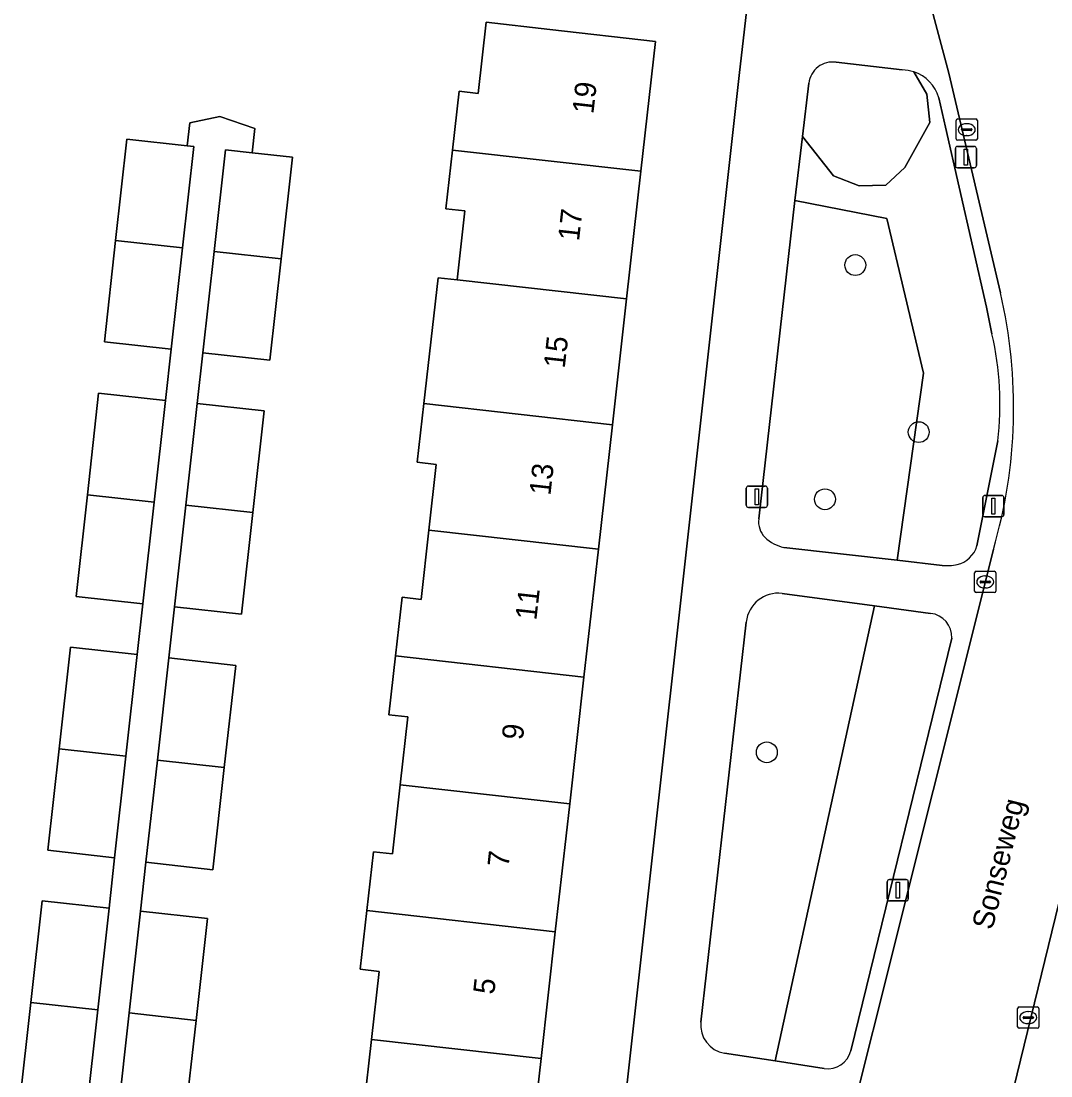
# Model space of a CAD drawing. Extents: x 162026 to 163502, y 387295 to 388169.
# Drawn here: x 162444.62 to 162492.97, y 387651.13 to 387700.63 of the extents above; entities that cross this region are included whole.
import ezdxf

# ---------------------------------------------------------------- set-up
doc = ezdxf.new("R2010")
doc.units = 0
for name, color, linetype in [('IMGEO_Boom', 7, 'Continuous'), ('IMGEO_Erf', 7, 'Continuous'), ('IMGEO_Groenvoorziening', 7, 'Continuous'), ('IMGEO_Kolk', 7, 'Continuous'), ('IMGEO_Lichtmast', 7, 'Continuous'), ('IMGEO_Openbare_ruimte_label', 7, 'Continuous'), ('IMGEO_Pand', 7, 'Continuous'), ('IMGEO_Pand_nummerreeks', 7, 'Continuous'), ('IMGEO_Rijbaan_lokaal_open', 7, 'Continuous'), ('IMGEO_Voetpad_open', 7, 'Continuous')]:
    doc.layers.add(name, color=color, linetype=linetype)

msp = doc.modelspace()

# ---------------------------------------------------------------- linework, layer by layer
at = {"layer": 'IMGEO_Boom'}
for centre in [(162483.784, 387689.183), (162486.762, 387681.344), (162482.36, 387678.19), (162479.63, 387666.315)]:
    msp.add_circle(centre, 0.489, dxfattribs=at)
at = {"layer": 'IMGEO_Erf'}
for points in [[(162471.82, 387639.553), (162478.34, 387698.075), (162483.821, 387745.82)], [(162460.711, 387649.647), (162461.071, 387652.841), (162461.43, 387656.029), (162460.536, 387656.13), (162460.847, 387658.889), (162461.158, 387661.648), (162462.052, 387661.547), (162462.417, 387664.785), (162462.776, 387667.976), (162461.882, 387668.077), (162462.193, 387670.836), (162462.504, 387673.595), (162463.398, 387673.494), (162463.764, 387676.741), (162464.112, 387679.827), (162463.218, 387679.928), (162463.529, 387682.687), (162464.194, 387688.589), (162465.088, 387688.488), (162465.452, 387691.722), (162464.558, 387691.823), (162464.869, 387694.582), (162465.18, 387697.341), (162466.074, 387697.24), (162466.45, 387700.58), (162469.441, 387700.243), (162474.409, 387699.683), (162473.722, 387693.585), (162473.047, 387687.592), (162472.382, 387681.69), (162471.723, 387675.844), (162471.046, 387669.839), (162470.376, 387663.889), (162469.7, 387657.892), (162469.03, 387651.945), (162468.359, 387645.992)], [(162444.545, 387649.799), (162445.077, 387654.579), (162445.608, 387659.349), (162448.749, 387659), (162449.012, 387661.368), (162445.872, 387661.718), (162446.401, 387666.478), (162446.932, 387671.249), (162450.073, 387670.899), (162450.338, 387673.285), (162447.198, 387673.634), (162447.729, 387678.404), (162448.259, 387683.175), (162451.4, 387682.825), (162451.668, 387685.229), (162448.527, 387685.579), (162449.057, 387690.338), (162449.586, 387695.099), (162452.42, 387694.784), (162452.54, 387695.863), (162453.951, 387696.158), (162455.587, 387695.598), (162455.462, 387694.457), (162457.357, 387694.245), (162456.824, 387689.475), (162456.293, 387684.719), (162453.153, 387685.07), (162452.886, 387682.687), (162456.027, 387682.336), (162455.494, 387677.566), (162454.961, 387672.794), (162451.821, 387673.144), (162451.553, 387670.744), (162454.693, 387670.393), (162454.159, 387665.603), (162453.623, 387660.805), (162450.482, 387661.156), (162450.226, 387658.862), (162453.367, 387658.511), (162452.833, 387653.731), (162452.298, 387648.942)]]:
    msp.add_lwpolyline(points, dxfattribs=at)
at = {"layer": 'IMGEO_Groenvoorziening'}
for points in [[(162485.989, 387698.352), (162482.88, 387698.703)], [(162486.535, 387698.254), (162487.144, 387697.197), (162487.29, 387695.879), (162486.104, 387693.77), (162485.226, 387692.936), (162483.966, 387692.906), (162482.766, 387693.375), (162481.306, 387695.213), (162480.953, 387692.213), (162485.262, 387691.368), (162486.986, 387684.115), (162485.754, 387675.329), (162487.867, 387675.09)], [(162487.144, 387697.197), (162486.535, 387698.254)], [(162481.601, 387697.723), (162481.306, 387695.213), (162482.766, 387693.375), (162483.966, 387692.906), (162485.226, 387692.936), (162486.104, 387693.77), (162487.29, 387695.879), (162487.144, 387697.197)], [(162489.943, 387687.203), (162488.021, 387695.657), (162487.707, 387697.035)], [(162486.986, 387684.115), (162485.262, 387691.368), (162480.953, 387692.213), (162479.249, 387677.274)], [(162490.199, 387685.954), (162489.943, 387687.203)], [(162480.436, 387675.932), (162485.754, 387675.329), (162486.986, 387684.115)], [(162489.496, 387676.007), (162490.475, 387680.93)], [(162484.685, 387673.193), (162480.348, 387673.775)], [(162477.646, 387652.197), (162480.015, 387651.832), (162484.685, 387673.193)], [(162487.322, 387672.835), (162484.685, 387673.193), (162480.015, 387651.832), (162482.329, 387651.474)], [(162478.662, 387672.431), (162476.532, 387653.657)], [(162483.572, 387652.305), (162488.31, 387671.677)]]:
    msp.add_lwpolyline(points, dxfattribs=at)
for centre, radius, start, end in [((162482.717, 387697.592), 1.123, 81.6353, 173.2851), ((162485.527, 387694.207), 4.171, 76.0118, 83.6372), ((162485.977, 387696.545), 1.798, 15.8266, 71.9212), ((162475.953, 387682.652), 14.624, 353.2385, 13.0504), ((162480.279, 387677.143), 1.038, 172.7608, 225.0207), ((162480.772, 387677.63), 1.731, 224.8641, 258.8108), ((162488.262, 387676.372), 1.286, 283.9313, 343.5339), ((162488.103, 387677.606), 2.527, 264.6516, 280.7084), ((162480.178, 387672.259), 1.525, 83.593, 173.5274), ((162487.21, 387671.739), 1.102, 356.7947, 84.1466), ((162477.849, 387653.507), 1.325, 173.4922, 261.1961), ((162482.497, 387652.568), 1.107, 261.2911, 346.2378)]:
    msp.add_arc(centre, radius, start, end, dxfattribs=at)
at = {"layer": 'IMGEO_Kolk'}
for p, q in [((162488.518, 387695.114), (162488.518, 387695.966)), ((162488.593, 387696.04), (162489.445, 387696.04)), ((162489.519, 387695.966), (162489.519, 387695.114)), ((162488.777, 387695.534), (162488.777, 387695.546)), ((162489.215, 387695.497), (162488.817, 387695.497)), ((162488.82, 387695.583), (162489.218, 387695.583)), ((162489.006, 387695.82), (162489.031, 387695.82)), ((162489.261, 387695.546), (162489.261, 387695.534)), ((162489.445, 387695.04), (162488.593, 387695.04)), ((162489.029, 387695.26), (162489.004, 387695.26)), ((162489.385, 387673.885), (162489.385, 387674.737)), ((162489.46, 387674.811), (162490.312, 387674.811)), ((162490.386, 387674.737), (162490.386, 387673.885)), ((162489.644, 387674.305), (162489.644, 387674.317)), ((162490.082, 387674.268), (162489.684, 387674.268)), ((162489.687, 387674.354), (162490.085, 387674.354)), ((162489.873, 387674.591), (162489.898, 387674.591)), ((162490.128, 387674.317), (162490.128, 387674.305)), ((162490.312, 387673.811), (162489.46, 387673.811)), ((162489.896, 387674.031), (162489.871, 387674.031)), ((162491.479, 387654.364), (162492.331, 387654.364)), ((162491.404, 387653.438), (162491.404, 387654.29)), ((162491.663, 387653.858), (162491.663, 387653.87)), ((162492.101, 387653.821), (162491.703, 387653.821)), ((162491.706, 387653.907), (162492.104, 387653.907)), ((162491.892, 387654.144), (162491.917, 387654.144)), ((162492.147, 387653.87), (162492.147, 387653.858)), ((162492.405, 387654.29), (162492.405, 387653.438)), ((162492.331, 387653.364), (162491.479, 387653.364)), ((162491.915, 387653.584), (162491.89, 387653.584))]:
    msp.add_line(p, q, dxfattribs=at)
for points in [[(162488.518, 387695.114), (162488.518, 387695.966)], [(162488.593, 387696.04), (162489.445, 387696.04)], [(162489.519, 387695.966), (162489.519, 387695.114)], [(162489.445, 387695.04), (162488.593, 387695.04)], [(162489.385, 387673.885), (162489.385, 387674.737)], [(162489.46, 387674.811), (162490.312, 387674.811)], [(162490.386, 387674.737), (162490.386, 387673.885)], [(162490.312, 387673.811), (162489.46, 387673.811)], [(162491.479, 387654.364), (162492.331, 387654.364)], [(162491.404, 387653.438), (162491.404, 387654.29)], [(162492.405, 387654.29), (162492.405, 387653.438)], [(162492.331, 387653.364), (162491.479, 387653.364)]]:
    msp.add_lwpolyline(points, dxfattribs=at)
for centre, radius, start, end in [((162488.595, 387695.964), 0.0765, 91.552, 178.448), ((162488.595, 387695.964), 0.0765, 91.552, 178.448), ((162489.443, 387695.964), 0.0765, 1.552, 88.448), ((162489.443, 387695.964), 0.0765, 1.552, 88.448), ((162488.817, 387695.543), 0.0403, 85.8775, 175.7526), ((162488.814, 387695.533), 0.0366, 178.938, 274.7102), ((162489.218, 387695.54), 0.043, 264.8664, 352.4533), ((162489.222, 387695.545), 0.0386, 1.7309, 96.639), ((162488.595, 387695.116), 0.0765, 181.552, 268.448), ((162488.595, 387695.116), 0.0765, 181.552, 268.448), ((162489.443, 387695.116), 0.0765, 271.552, 358.448), ((162489.443, 387695.116), 0.0765, 271.552, 358.448), ((162489.462, 387674.735), 0.0765, 91.552, 178.448), ((162489.462, 387674.735), 0.0765, 91.552, 178.448), ((162490.31, 387674.735), 0.0765, 1.552, 88.448), ((162490.31, 387674.735), 0.0765, 1.552, 88.448), ((162489.684, 387674.314), 0.0403, 85.8775, 175.7526), ((162489.681, 387674.304), 0.0366, 178.938, 274.7102), ((162490.085, 387674.311), 0.043, 264.8664, 352.4533), ((162490.089, 387674.316), 0.0386, 1.7309, 96.639), ((162489.462, 387673.887), 0.0765, 181.552, 268.448), ((162489.462, 387673.887), 0.0765, 181.552, 268.448), ((162490.31, 387673.887), 0.0765, 271.552, 358.448), ((162490.31, 387673.887), 0.0765, 271.552, 358.448), ((162491.481, 387654.288), 0.0765, 91.552, 178.448), ((162491.481, 387654.288), 0.0765, 91.552, 178.448), ((162492.329, 387654.288), 0.0765, 1.552, 88.448), ((162492.329, 387654.288), 0.0765, 1.552, 88.448), ((162491.703, 387653.867), 0.0403, 85.8775, 175.7526), ((162491.7, 387653.857), 0.0366, 178.938, 274.7102), ((162492.104, 387653.864), 0.043, 264.8664, 352.4533), ((162492.108, 387653.869), 0.0386, 1.7309, 96.639), ((162491.481, 387653.44), 0.0765, 181.552, 268.448), ((162491.481, 387653.44), 0.0765, 181.552, 268.448), ((162492.329, 387653.44), 0.0765, 271.552, 358.448), ((162492.329, 387653.44), 0.0765, 271.552, 358.448)]:
    msp.add_arc(centre, radius, start, end, dxfattribs=at)
for centre, major_axis, ratio, start_param, end_param in [((162489.005, 387695.54), (-0.387, 0.002), 0.722429, 4.712389, 7.853982), ((162489.03, 387695.54), (-0.39, 0.002), 0.717154, 1.570796, 4.712389), ((162489.872, 387674.311), (-0.387, 0.002), 0.722429, 4.712389, 7.853982), ((162489.897, 387674.311), (-0.39, 0.002), 0.717154, 1.570796, 4.712389), ((162491.891, 387653.864), (-0.387, 0.002), 0.722429, 4.712389, 7.853982), ((162491.916, 387653.864), (-0.39, 0.002), 0.717154, 1.570796, 4.712389)]:
    msp.add_ellipse(centre, major_axis=major_axis, ratio=ratio, start_param=start_param, end_param=end_param, dxfattribs=at)
at = {"layer": 'IMGEO_Lichtmast'}
for p, q in [((162488.483, 387693.849), (162488.483, 387694.649)), ((162488.483, 387694.649), (162488.483, 387693.849)), ((162488.583, 387694.749), (162489.373, 387694.749)), ((162489.373, 387694.749), (162488.583, 387694.749)), ((162489.473, 387694.649), (162489.473, 387693.849)), ((162489.473, 387693.849), (162489.473, 387694.649)), ((162489.373, 387693.749), (162488.583, 387693.749)), ((162488.583, 387693.749), (162489.373, 387693.749)), ((162478.665, 387677.907), (162478.665, 387678.707)), ((162478.665, 387678.707), (162478.665, 387677.907)), ((162478.765, 387678.807), (162479.555, 387678.807)), ((162479.555, 387678.807), (162478.765, 387678.807)), ((162479.655, 387678.707), (162479.655, 387677.907)), ((162479.655, 387677.907), (162479.655, 387678.707)), ((162489.771, 387677.469), (162489.771, 387678.269)), ((162489.771, 387678.269), (162489.771, 387677.469)), ((162489.871, 387678.369), (162490.661, 387678.369)), ((162490.661, 387678.369), (162489.871, 387678.369)), ((162490.761, 387678.269), (162490.761, 387677.469)), ((162490.761, 387677.469), (162490.761, 387678.269)), ((162479.555, 387677.807), (162478.765, 387677.807)), ((162478.765, 387677.807), (162479.555, 387677.807)), ((162490.661, 387677.369), (162489.871, 387677.369)), ((162489.871, 387677.369), (162490.661, 387677.369)), ((162485.383, 387660.343), (162486.173, 387660.343)), ((162486.173, 387660.343), (162485.383, 387660.343)), ((162485.283, 387659.443), (162485.283, 387660.243)), ((162485.283, 387660.243), (162485.283, 387659.443)), ((162486.273, 387660.243), (162486.273, 387659.443)), ((162486.273, 387659.443), (162486.273, 387660.243)), ((162486.173, 387659.343), (162485.383, 387659.343)), ((162485.383, 387659.343), (162486.173, 387659.343))]:
    msp.add_line(p, q, dxfattribs=at)
for points in [[(162488.903, 387694.624), (162489.053, 387694.624), (162489.053, 387693.874), (162488.903, 387693.874), (162488.903, 387694.624)], [(162479.085, 387678.682), (162479.235, 387678.682), (162479.235, 387677.932), (162479.085, 387677.932), (162479.085, 387678.682)], [(162490.191, 387678.244), (162490.341, 387678.244), (162490.341, 387677.494), (162490.191, 387677.494), (162490.191, 387678.244)], [(162485.703, 387660.218), (162485.853, 387660.218), (162485.853, 387659.468), (162485.703, 387659.468), (162485.703, 387660.218)]]:
    msp.add_lwpolyline(points, dxfattribs=at)
for centre, start, end in [((162488.583, 387694.649), 90, 180), ((162488.583, 387694.649), 90, 180), ((162489.373, 387694.649), 0, 90), ((162489.373, 387694.649), 360, 90), ((162488.583, 387693.849), 180, 270), ((162488.583, 387693.849), 180, 270), ((162489.373, 387693.849), 270, 0), ((162489.373, 387693.849), 270, 0), ((162478.765, 387678.707), 90, 180), ((162478.765, 387678.707), 90, 180), ((162479.555, 387678.707), 0, 90), ((162479.555, 387678.707), 360, 90), ((162489.871, 387678.269), 90, 180), ((162489.871, 387678.269), 90, 180), ((162490.661, 387678.269), 0, 90), ((162490.661, 387678.269), 360, 90), ((162478.765, 387677.907), 180, 270), ((162478.765, 387677.907), 180, 270), ((162479.555, 387677.907), 270, 0), ((162479.555, 387677.907), 270, 0), ((162489.871, 387677.469), 180, 270), ((162489.871, 387677.469), 180, 270), ((162490.661, 387677.469), 270, 0), ((162490.661, 387677.469), 270, 0), ((162485.383, 387660.243), 90, 180), ((162485.383, 387660.243), 90, 180), ((162486.173, 387660.243), 0, 90), ((162486.173, 387660.243), 360, 90), ((162485.383, 387659.443), 180, 270), ((162485.383, 387659.443), 180, 270), ((162486.173, 387659.443), 270, 0), ((162486.173, 387659.443), 270, 0)]:
    msp.add_arc(centre, 0.1, start, end, dxfattribs=at)
at = {"layer": 'IMGEO_Pand'}
for points in [[(162465.18, 387697.341), (162464.869, 387694.582), (162473.722, 387693.585), (162474.409, 387699.683), (162469.441, 387700.243), (162466.45, 387700.58), (162466.074, 387697.24)], [(162452.727, 387694.75), (162452.42, 387694.784), (162449.586, 387695.099), (162449.057, 387690.338), (162452.197, 387689.989)], [(162455.462, 387694.457), (162454.216, 387694.596), (162453.684, 387689.825), (162456.824, 387689.475), (162457.357, 387694.245)], [(162464.558, 387691.823), (162465.452, 387691.722), (162465.088, 387688.488), (162473.047, 387687.592), (162473.722, 387693.585), (162464.869, 387694.582)], [(162452.197, 387689.989), (162449.057, 387690.338), (162448.527, 387685.579), (162451.668, 387685.229)], [(162456.824, 387689.475), (162453.684, 387689.825), (162453.153, 387685.07), (162456.293, 387684.719)], [(162473.047, 387687.592), (162465.088, 387688.488), (162464.194, 387688.589), (162463.529, 387682.687), (162472.382, 387681.69)], [(162451.4, 387682.825), (162448.259, 387683.175), (162447.729, 387678.404), (162450.869, 387678.055)], [(162452.886, 387682.687), (162452.354, 387677.917), (162455.494, 387677.566), (162456.027, 387682.336)], [(162463.218, 387679.928), (162464.112, 387679.827), (162463.764, 387676.741), (162471.723, 387675.844), (162472.382, 387681.69), (162463.529, 387682.687)], [(162450.869, 387678.055), (162447.729, 387678.404), (162447.198, 387673.634), (162450.338, 387673.285)], [(162455.494, 387677.566), (162452.354, 387677.917), (162451.821, 387673.144), (162454.961, 387672.794)], [(162462.504, 387673.595), (162462.193, 387670.836), (162471.046, 387669.839), (162471.723, 387675.844), (162463.764, 387676.741), (162463.398, 387673.494)], [(162450.073, 387670.899), (162446.932, 387671.249), (162446.401, 387666.478), (162449.542, 387666.128)], [(162451.553, 387670.744), (162451.018, 387665.954), (162454.159, 387665.603), (162454.693, 387670.393)], [(162461.882, 387668.077), (162462.776, 387667.976), (162462.417, 387664.785), (162470.376, 387663.889), (162471.046, 387669.839), (162462.193, 387670.836)], [(162449.542, 387666.128), (162446.401, 387666.478), (162445.872, 387661.718), (162449.012, 387661.368)], [(162454.159, 387665.603), (162451.018, 387665.954), (162450.482, 387661.156), (162453.623, 387660.805)], [(162461.158, 387661.648), (162460.847, 387658.889), (162469.7, 387657.892), (162470.376, 387663.889), (162462.417, 387664.785), (162462.052, 387661.547)], [(162448.749, 387659), (162445.608, 387659.349), (162445.077, 387654.579), (162448.218, 387654.229)], [(162450.226, 387658.862), (162449.692, 387654.082), (162452.833, 387653.731), (162453.367, 387658.511)], [(162460.536, 387656.13), (162461.43, 387656.029), (162461.071, 387652.841), (162469.03, 387651.945), (162469.7, 387657.892), (162460.847, 387658.889)], [(162448.218, 387654.229), (162445.077, 387654.579), (162444.545, 387649.799), (162447.686, 387649.449)], [(162452.833, 387653.731), (162449.692, 387654.082), (162449.158, 387649.292), (162452.298, 387648.942)], [(162459.817, 387649.748), (162459.506, 387646.989), (162468.359, 387645.992), (162469.03, 387651.945), (162461.071, 387652.841), (162460.711, 387649.647)]]:
    msp.add_lwpolyline(points, close=True, dxfattribs=at)
at = {"layer": 'IMGEO_Rijbaan_lokaal_open'}
for points in [[(162486.11, 387705.881), (162486.539, 387704.356), (162488.177, 387698.19), (162490.602, 387687.877)], [(162486.172, 387630.015), (162486.508, 387631.255), (162487.791, 387636.482), (162497.263, 387675.316), (162498.286, 387679.137), (162498.305, 387679.17), (162498.449, 387679.931), (162498.615, 387681.926), (162498.638, 387684.945)], [(162490.267, 387675.831), (162478.964, 387630.648)]]:
    msp.add_lwpolyline(points, dxfattribs=at)
msp.add_arc((162467.417, 387682.494), 23.801, 343.743, 13.071, dxfattribs=at)
at = {"layer": 'IMGEO_Voetpad_open'}
for points in [[(162487.392, 387776.92), (162486.062, 387765.339), (162484.018, 387747.533), (162483.821, 387745.82), (162478.34, 387698.075), (162471.82, 387639.553), (162471.648, 387638.013), (162471.035, 387632.515)], [(162490.602, 387687.877), (162488.177, 387698.19), (162486.539, 387704.356), (162486.11, 387705.881)], [(162482.88, 387698.703), (162485.989, 387698.352)], [(162479.249, 387677.274), (162480.953, 387692.213), (162481.306, 387695.213), (162481.601, 387697.723)], [(162487.707, 387697.035), (162488.021, 387695.657), (162489.943, 387687.203), (162490.199, 387685.954)], [(162449.158, 387649.292), (162449.692, 387654.082), (162450.226, 387658.862), (162450.482, 387661.156), (162451.018, 387665.954), (162451.553, 387670.744), (162451.821, 387673.144), (162452.354, 387677.917), (162452.886, 387682.687), (162453.153, 387685.07), (162453.684, 387689.825), (162454.216, 387694.596), (162455.462, 387694.457), (162455.587, 387695.598), (162453.951, 387696.158), (162452.54, 387695.863), (162452.42, 387694.784), (162452.727, 387694.75), (162452.197, 387689.989), (162451.668, 387685.229), (162451.4, 387682.825), (162450.869, 387678.055), (162450.338, 387673.285), (162450.073, 387670.899), (162449.542, 387666.128), (162449.012, 387661.368), (162448.749, 387659), (162448.218, 387654.229), (162447.686, 387649.449)], [(162498.638, 387684.945), (162498.615, 387681.926), (162498.449, 387679.931), (162498.305, 387679.17), (162498.286, 387679.137), (162497.263, 387675.316), (162487.791, 387636.482), (162486.508, 387631.255), (162486.172, 387630.015)], [(162490.475, 387680.93), (162489.496, 387676.007)], [(162478.964, 387630.648), (162490.267, 387675.831)], [(162487.867, 387675.09), (162485.754, 387675.329), (162480.436, 387675.932)], [(162480.348, 387673.775), (162484.685, 387673.193)], [(162484.685, 387673.193), (162487.322, 387672.835)], [(162476.532, 387653.657), (162478.662, 387672.431)], [(162488.31, 387671.677), (162483.572, 387652.305)], [(162482.329, 387651.474), (162480.015, 387651.832), (162477.646, 387652.197)]]:
    msp.add_lwpolyline(points, dxfattribs=at)
for centre, radius, start, end in [((162482.717, 387697.592), 1.123, 81.6353, 173.2851), ((162485.527, 387694.207), 4.171, 76.0118, 83.6372), ((162485.977, 387696.545), 1.798, 15.8266, 71.9212), ((162467.417, 387682.494), 23.801, 343.743, 13.071), ((162475.953, 387682.652), 14.624, 353.2385, 13.0504), ((162480.279, 387677.143), 1.038, 172.7608, 225.0207), ((162480.772, 387677.63), 1.731, 224.8641, 258.8108), ((162488.262, 387676.372), 1.286, 283.9313, 343.5339), ((162488.103, 387677.606), 2.527, 264.6516, 280.7084), ((162480.178, 387672.259), 1.525, 83.593, 173.5274), ((162487.21, 387671.739), 1.102, 356.7947, 84.1466), ((162477.849, 387653.507), 1.325, 173.4922, 261.1961), ((162482.497, 387652.568), 1.107, 261.2911, 346.2378)]:
    msp.add_arc(centre, radius, start, end, dxfattribs=at)

# ---------------------------------------------------------------- texts
at = {"layer": 'IMGEO_Openbare_ruimte_label'}
msp.add_text('Sonseweg', height=1, rotation=75.9916, dxfattribs=at).set_placement((162490.217, 387657.936))
at = {"layer": 'IMGEO_Pand_nummerreeks'}
for s, rotation, p in [('19', 83.5712, (162471.486, 387696.25)), ('17', 83.5712, (162470.813, 387690.281)), ('15', 83.5716, (162470.141, 387684.311)), ('13', 83.5712, (162469.468, 387678.342)), ('11', 83.5712, (162468.809, 387672.486)), ('9', 83.5712, (162468.175, 387666.86)), ('7', 83.5712, (162467.502, 387660.89)), ('5', 83.5712, (162466.83, 387654.921))]:
    msp.add_text(s, height=1, rotation=rotation, dxfattribs=at).set_placement(p)

doc.saveas('drawing.dxf')
